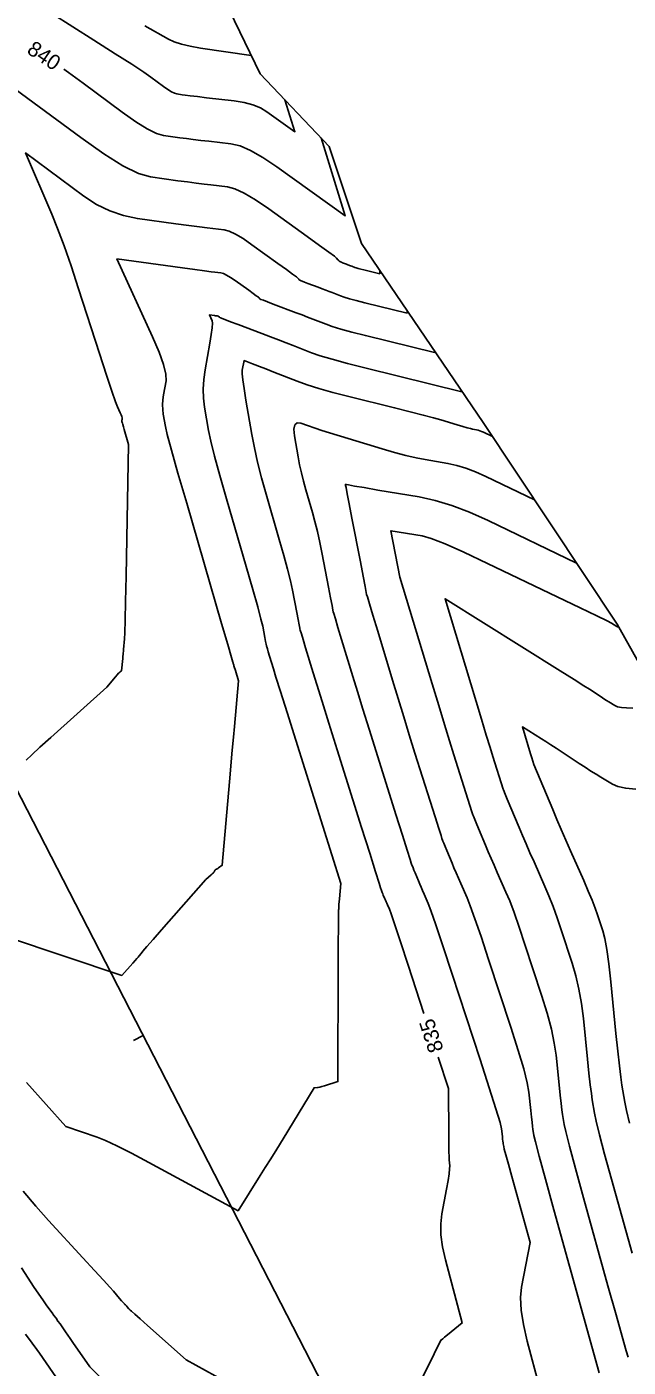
# Model space of a CAD drawing. Extents: x 1715724 to 1716561, y 394063 to 395906.
# Drawn here: x 1716015.3 to 1716070.7, y 395089 to 395212.3 of the extents above; entities that cross this region are included whole.
import ezdxf

# ---------------------------------------------------------------- set-up
doc = ezdxf.new("R2010")
doc.units = 0
for name, color, linetype in [('DT_X_Contour_Major', 7, 'Continuous'), ('DT_X_Contour_Minor', 7, 'Continuous'), ('DT_X_TIN_Hull', 7, 'Continuous'), ('GE_P_CL_10', 7, 'Continuous')]:
    doc.layers.add(name, color=color, linetype=linetype)

msp = doc.modelspace()

# ---------------------------------------------------------------- linework, layer by layer
at = {"layer": 'DT_X_Contour_Major'}
for points in [[(1716018.73, 395208.41), (1716019.18, 395208.1), (1716020.51, 395207.13), (1716024.11, 395204.46), (1716025.36, 395203.58), (1716026.42, 395202.92), (1716027.28, 395202.5), (1716027.93, 395202.31), (1716029.43, 395202.1), (1716030.02, 395202.03), (1716030.65, 395201.94), (1716031.34, 395201.86), (1716032.08, 395201.78), (1716034.12, 395201.54), (1716034.96, 395201.35), (1716035.94, 395200.93), (1716037.07, 395200.29), (1716038.35, 395199.43), (1716044.64, 395194.91), (1716042.42, 395202.1)], [(1716051.9, 395121.49), (1716050.44, 395125.94), (1716049.73, 395128.09), (1716049.21, 395129.66), (1716048.87, 395130.67), (1716048.71, 395131.1), (1716048.54, 395131.5), (1716048.47, 395131.65), (1716048.41, 395131.79), (1716048.35, 395131.92), (1716048.3, 395132.05), (1716048.15, 395132.4), (1716048.1, 395132.52), (1716048.06, 395132.63), (1716048.02, 395132.74), (1716047.99, 395132.83), (1716047.9, 395133.08), (1716047.77, 395133.49), (1716047.44, 395134.55), (1716046.9, 395136.26), (1716046.15, 395138.62), (1716043.9, 395145.78), (1716043.13, 395148.23), (1716042.51, 395150.23), (1716042.03, 395151.78), (1716041.7, 395152.86), (1716041, 395155.16), (1716040.77, 395155.91), (1716040.61, 395156.45), (1716040.51, 395156.78), (1716040.48, 395156.89), (1716040.48, 395156.89), (1716040.46, 395156.98), (1716040.4, 395157.27), (1716040.31, 395157.75), (1716040.18, 395158.42), (1716039.79, 395160.46), (1716039.6, 395161.33), (1716039.34, 395162.4), (1716039, 395163.66), (1716038.58, 395165.13), (1716037.36, 395169.3), (1716036.94, 395170.81), (1716036.58, 395172.24), (1716036.28, 395173.56), (1716036.04, 395174.79), (1716035.51, 395177.95), (1716035.33, 395179.01), (1716035.22, 395179.82), (1716035.17, 395180.38), (1716035.17, 395180.7), (1716035.33, 395181.59), (1716036.11, 395181.3), (1716036.36, 395181.2), (1716036.77, 395181.04), (1716037.33, 395180.82), (1716038.06, 395180.54), (1716040.22, 395179.69), (1716041.13, 395179.36), (1716042.22, 395179.02), (1716043.51, 395178.66), (1716044.99, 395178.28), (1716049.19, 395177.25), (1716050.64, 395176.88), (1716051.83, 395176.58), (1716052.77, 395176.33), (1716053.46, 395176.13), (1716054.96, 395175.67), (1716055.47, 395175.52), (1716055.87, 395175.4), (1716056.17, 395175.33), (1716056.37, 395175.28), (1716056.75, 395175.22), (1716056.9, 395175.19), (1716057.05, 395175.14), (1716057.21, 395175.08), (1716057.38, 395175), (1716058.2, 395174.61)], [(1716071.39, 395142.15), (1716070.47, 395142.24), (1716069.76, 395142.39), (1716069.25, 395142.6), (1716068.17, 395143.26), (1716067.74, 395143.53), (1716067.27, 395143.82), (1716066.75, 395144.16), (1716066.19, 395144.52), (1716064.07, 395145.91), (1716063.57, 395146.24), (1716063.12, 395146.53), (1716062.71, 395146.78), (1716060.96, 395147.88), (1716061.71, 395145.4), (1716061.83, 395145.02), (1716062.02, 395144.41), (1716063.75, 395140.28), (1716064.13, 395139.37), (1716064.53, 395138.44), (1716064.96, 395137.46), (1716065.4, 395136.46), (1716066.61, 395133.73), (1716067.03, 395132.76), (1716067.38, 395131.92), (1716067.67, 395131.19), (1716067.88, 395130.58), (1716068.36, 395129.11), (1716068.54, 395128.41), (1716068.72, 395127.39), (1716068.91, 395126.07), (1716069.09, 395124.43), (1716069.57, 395119.66), (1716069.74, 395118.03), (1716069.89, 395116.69), (1716070.02, 395115.65), (1716070.13, 395114.91), (1716070.38, 395113.33), (1716070.54, 395112.56), (1716070.81, 395111.4)], [(1716051.48, 395087.48), (1716052.27, 395089.05), (1716052.84, 395090.19), (1716053.19, 395090.9), (1716053.32, 395091.17), (1716053.45, 395091.44), (1716053.46, 395091.45), (1716053.5, 395091.48), (1716053.62, 395091.57), (1716053.8, 395091.72), (1716054.06, 395091.93), (1716055.43, 395093.03), (1716053.88, 395098.83), (1716053.61, 395100.03), (1716053.46, 395101.13), (1716053.44, 395102.13), (1716053.54, 395103.05), (1716053.98, 395105.35), (1716054.12, 395106.13), (1716054.21, 395106.75), (1716054.26, 395107.2), (1716054.27, 395107.48), (1716054.23, 395108.02), (1716054.21, 395108.32), (1716054.2, 395108.79), (1716054.19, 395109.45), (1716054.18, 395110.28), (1716054.15, 395114.6), (1716053.21, 395117.49)], [(1716015, 395105.15), (1716016.15, 395103.76), (1716017.32, 395102.44), (1716020.49, 395099.01), (1716021.56, 395097.86), (1716022.38, 395096.96), (1716022.96, 395096.33), (1716023.3, 395095.95), (1716023.87, 395095.28), (1716024.06, 395095.07), (1716024.2, 395094.91), (1716024.29, 395094.81), (1716024.32, 395094.77), (1716024.34, 395094.75), (1716024.35, 395094.74), (1716024.36, 395094.73), (1716024.37, 395094.72), (1716024.38, 395094.71), (1716024.42, 395094.67), (1716024.44, 395094.66), (1716024.47, 395094.63), (1716024.5, 395094.59), (1716024.53, 395094.55), (1716024.71, 395094.32), (1716024.85, 395094.2), (1716024.97, 395094.1), (1716025.28, 395093.83), (1716025.77, 395093.4), (1716026.44, 395092.8), (1716030.01, 395089.64), (1716034.44, 395087.17)]]:
    msp.add_lwpolyline(points, dxfattribs=at)
at = {"layer": 'DT_X_Contour_Minor'}
for points in [[(1716015.7, 395214.75), (1716021.51, 395211.08), (1716023.47, 395209.84), (1716025, 395208.86), (1716026.09, 395208.14), (1716026.74, 395207.68), (1716027.91, 395206.82), (1716028.31, 395206.54), (1716028.65, 395206.32), (1716028.93, 395206.19), (1716029.14, 395206.13), (1716029.62, 395206.06), (1716029.9, 395206.02), (1716030.37, 395205.97), (1716031.04, 395205.89), (1716031.89, 395205.79), (1716034.43, 395205.5), (1716035.33, 395205.36), (1716036.13, 395205.14), (1716036.84, 395204.85), (1716037.44, 395204.49), (1716040.01, 395202.65), (1716039.1, 395205.58)], [(1716026.2, 395212.41), (1716028.37, 395211.18), (1716028.91, 395210.93), (1716029.57, 395210.71), (1716030.38, 395210.52), (1716031.31, 395210.35), (1716035.99, 395209.67)], [(1716014.27, 395206.58), (1716020.31, 395202.11), (1716022.41, 395200.62), (1716024.18, 395199.52), (1716025.62, 395198.81), (1716026.73, 395198.49), (1716029.24, 395198.15), (1716030.13, 395198.03), (1716030.93, 395197.92), (1716031.65, 395197.83), (1716032.27, 395197.76), (1716033.81, 395197.58), (1716034.48, 395197.41), (1716035.34, 395197.01), (1716036.38, 395196.39), (1716037.61, 395195.55), (1716041.13, 395193.02), (1716042.29, 395192.19), (1716043.13, 395191.57), (1716043.65, 395191.19), (1716043.86, 395191.02), (1716043.98, 395190.88), (1716044.02, 395190.83), (1716044.05, 395190.79), (1716044.08, 395190.76), (1716044.09, 395190.75), (1716044.12, 395190.72), (1716044.15, 395190.71), (1716044.2, 395190.68), (1716044.29, 395190.65), (1716044.41, 395190.6), (1716044.77, 395190.47), (1716044.9, 395190.42), (1716045.14, 395190.32), (1716045.25, 395190.28), (1716045.53, 395190.17), (1716045.66, 395190.13), (1716045.85, 395190.07), (1716046.08, 395190.01), (1716046.37, 395189.94), (1716047.83, 395189.58), (1716047.84, 395189.6), (1716047.84, 395189.62), (1716047.84, 395189.63), (1716047.84, 395189.66), (1716047.84, 395189.7), (1716047.84, 395189.89)], [(1716015.27, 395144.83), (1716015.79, 395145.31), (1716016.54, 395146), (1716017.53, 395146.89), (1716022.69, 395151.53), (1716023.5, 395152.49), (1716023.66, 395152.67), (1716023.78, 395152.81), (1716023.87, 395152.9), (1716023.92, 395152.94), (1716024.06, 395153.04), (1716024.16, 395154.18), (1716024.18, 395154.4), (1716024.19, 395154.55), (1716024.2, 395154.67), (1716024.2, 395154.67), (1716024.21, 395154.71), (1716024.22, 395154.81), (1716024.23, 395154.99), (1716024.32, 395155.98), (1716024.35, 395156.55), (1716024.38, 395157.7), (1716024.42, 395159.43), (1716024.47, 395161.74), (1716024.69, 395173.88), (1716024.29, 395175.25), (1716024.22, 395175.51), (1716024.16, 395175.71), (1716024.13, 395175.84), (1716024.11, 395175.91), (1716024.09, 395176), (1716024.09, 395176.04), (1716024.09, 395176.08), (1716024.09, 395176.12), (1716024.1, 395176.16), (1716024.12, 395176.27), (1716024.11, 395176.33), (1716024.08, 395176.44), (1716024.02, 395176.59), (1716023.93, 395176.78), (1716023.67, 395177.35), (1716023.5, 395177.81), (1716023.16, 395178.79), (1716022.68, 395180.26), (1716022.03, 395182.24), (1716020.1, 395188.2), (1716019.41, 395190.31), (1716018.76, 395192.16), (1716018.17, 395193.75), (1716017.63, 395195.08), (1716015.22, 395200.71), (1716020.58, 395196.74), (1716021.75, 395195.97), (1716022.97, 395195.37), (1716024.22, 395194.94), (1716025.52, 395194.67), (1716029.04, 395194.19), (1716030.24, 395194.03), (1716031.22, 395193.9), (1716031.95, 395193.8), (1716032.46, 395193.74), (1716033.5, 395193.62), (1716033.95, 395193.5), (1716034.53, 395193.24), (1716035.24, 395192.82), (1716036.06, 395192.25), (1716038.44, 395190.54), (1716039.23, 395189.98), (1716039.8, 395189.56), (1716040.15, 395189.3), (1716040.29, 395189.19), (1716040.37, 395189.09), (1716040.42, 395189.03), (1716040.44, 395189.02), (1716040.45, 395189.01), (1716040.46, 395188.99), (1716040.52, 395188.97), (1716040.89, 395188.82), (1716041.2, 395188.7), (1716042.17, 395188.34), (1716042.52, 395188.21), (1716042.85, 395188.08), (1716043.16, 395187.96), (1716043.46, 395187.85), (1716044.2, 395187.55), (1716044.55, 395187.43), (1716045.04, 395187.28), (1716045.67, 395187.11), (1716046.44, 395186.92), (1716050.34, 395185.96), (1716050.35, 395185.98), (1716050.35, 395185.99), (1716050.35, 395186), (1716050.35, 395186.02), (1716050.35, 395186.05), (1716050.36, 395186.19)], [(1716013.56, 395128.54), (1716024.09, 395125.01), (1716025.1, 395126.14), (1716025.3, 395126.37), (1716025.46, 395126.55), (1716025.59, 395126.7), (1716025.67, 395126.8), (1716025.85, 395127.03), (1716026.02, 395127.23), (1716026.39, 395127.66), (1716026.97, 395128.31), (1716027.74, 395129.19), (1716031.82, 395133.82), (1716032.31, 395134.26), (1716032.4, 395134.35), (1716032.48, 395134.42), (1716032.53, 395134.49), (1716032.57, 395134.54), (1716032.63, 395134.65), (1716032.66, 395134.69), (1716032.68, 395134.72), (1716032.7, 395134.75), (1716032.73, 395134.76), (1716032.78, 395134.79), (1716032.81, 395134.8), (1716032.85, 395134.83), (1716032.91, 395134.86), (1716032.97, 395134.9), (1716033.32, 395135.14), (1716033.99, 395142.82), (1716034.25, 395145.74), (1716034.36, 395146.92), (1716034.45, 395147.92), (1716034.83, 395152.12), (1716034.53, 395153.08), (1716034.43, 395153.4), (1716034.4, 395153.5), (1716034.38, 395153.56), (1716034.36, 395153.64), (1716034.35, 395153.67), (1716034.34, 395153.7), (1716034.34, 395153.71), (1716034.33, 395153.71), (1716034.33, 395153.72), (1716034.33, 395153.73), (1716034.32, 395153.77), (1716034.31, 395153.85), (1716034.19, 395154.27), (1716033.84, 395155.45), (1716033.27, 395157.41), (1716030.05, 395168.46), (1716029.25, 395171.24), (1716028.65, 395173.35), (1716028.26, 395174.78), (1716028.09, 395175.54), (1716027.9, 395176.65), (1716027.85, 395177.08), (1716027.83, 395177.52), (1716027.86, 395177.98), (1716027.93, 395178.45), (1716028.15, 395179.73), (1716028.14, 395180.34), (1716027.93, 395181.22), (1716027.52, 395182.36), (1716026.91, 395183.77), (1716023.62, 395190.95), (1716029.66, 395190.12), (1716030.81, 395189.97), (1716031.7, 395189.85), (1716032.31, 395189.77), (1716032.65, 395189.72), (1716033.19, 395189.66), (1716033.43, 395189.6), (1716033.73, 395189.46), (1716034.09, 395189.24), (1716034.52, 395188.95), (1716035.76, 395188.06), (1716036.17, 395187.77), (1716036.46, 395187.55), (1716036.65, 395187.42), (1716036.72, 395187.36), (1716036.76, 395187.31), (1716036.78, 395187.29), (1716036.79, 395187.28), (1716036.8, 395187.27), (1716036.8, 395187.26), (1716036.81, 395187.25), (1716036.89, 395187.22), (1716037.11, 395187.14), (1716037.48, 395187), (1716038, 395186.8), (1716040.14, 395186), (1716040.68, 395185.79), (1716041.18, 395185.59), (1716041.66, 395185.41), (1716042.88, 395184.93), (1716043.45, 395184.73), (1716044.24, 395184.49), (1716045.26, 395184.22), (1716046.51, 395183.9), (1716052.86, 395182.34), (1716052.87, 395182.35), (1716052.87, 395182.36), (1716052.87, 395182.37), (1716052.87, 395182.38), (1716052.87, 395182.4), (1716052.87, 395182.49)], [(1716015.31, 395115.15), (1716018.92, 395111.09), (1716021.82, 395110.12), (1716022.58, 395109.82), (1716023.63, 395109.33), (1716024.96, 395108.66), (1716026.58, 395107.8), (1716034.78, 395103.35), (1716036.83, 395106.58), (1716037.29, 395107.32), (1716037.8, 395108.13), (1716038.34, 395109.01), (1716038.93, 395109.98), (1716041.78, 395114.67), (1716042.08, 395114.69), (1716042.17, 395114.7), (1716042.31, 395114.73), (1716042.5, 395114.79), (1716042.74, 395114.86), (1716043.97, 395115.23), (1716044.01, 395125.97), (1716044.01, 395127.99), (1716044.02, 395129.46), (1716044.02, 395130.37), (1716044.03, 395130.74), (1716044.04, 395130.96), (1716044.04, 395131.04), (1716044.05, 395131.11), (1716044.05, 395131.17), (1716044.05, 395131.22), (1716044.05, 395131.35), (1716044.05, 395131.43), (1716044.06, 395131.57), (1716044.08, 395131.78), (1716044.11, 395132.06), (1716044.24, 395133.48), (1716040.09, 395146.66), (1716039.29, 395149.19), (1716038.69, 395151.13), (1716038.27, 395152.47), (1716038.04, 395153.21), (1716037.68, 395154.4), (1716037.56, 395154.79), (1716037.48, 395155.07), (1716037.42, 395155.24), (1716037.41, 395155.3), (1716037.4, 395155.35), (1716037.37, 395155.5), (1716037.32, 395155.75), (1716037.25, 395156.1), (1716037.05, 395157.16), (1716036.89, 395157.8), (1716036.59, 395158.92), (1716036.13, 395160.54), (1716035.53, 395162.64), (1716033.71, 395168.88), (1716033.09, 395171.03), (1716032.61, 395172.79), (1716032.27, 395174.17), (1716032.07, 395175.17), (1716031.7, 395177.3), (1716031.6, 395178.12), (1716031.58, 395178.96), (1716031.63, 395179.84), (1716031.75, 395180.74), (1716032.19, 395183.19), (1716032.32, 395184), (1716032.4, 395184.62), (1716032.43, 395185.04), (1716032.4, 395185.25), (1716032.15, 395185.8), (1716032.61, 395185.74), (1716032.7, 395185.72), (1716032.77, 395185.72), (1716032.84, 395185.71), (1716032.88, 395185.7), (1716032.9, 395185.7), (1716032.92, 395185.69), (1716032.95, 395185.67), (1716033.08, 395185.58), (1716033.11, 395185.56), (1716033.13, 395185.54), (1716033.14, 395185.53), (1716033.15, 395185.53), (1716033.15, 395185.52), (1716033.15, 395185.52), (1716033.15, 395185.52), (1716033.15, 395185.52), (1716033.16, 395185.52), (1716033.56, 395185.37), (1716034.07, 395185.17), (1716034.79, 395184.9), (1716036.96, 395184.08), (1716037.76, 395183.78), (1716038.5, 395183.5), (1716039.2, 395183.23), (1716039.86, 395182.97), (1716041.55, 395182.31), (1716042.34, 395182.04), (1716043.44, 395181.71), (1716044.86, 395181.32), (1716046.58, 395180.89), (1716055.38, 395178.72), (1716055.38, 395178.73), (1716055.38, 395178.78)], [(1716062.55, 395087.1), (1716061.41, 395091.36), (1716061.06, 395092.87), (1716060.85, 395094.2), (1716060.79, 395095.35), (1716060.89, 395096.31), (1716061.67, 395100.42), (1716059.98, 395106.49), (1716059.67, 395107.64), (1716059.44, 395108.49), (1716059.29, 395109.03), (1716059.24, 395109.27), (1716059.2, 395109.5), (1716059.18, 395109.6), (1716059.16, 395109.76), (1716059.14, 395109.95), (1716059.12, 395110.19), (1716059.05, 395110.88), (1716058.9, 395111.48), (1716058.53, 395112.74), (1716057.91, 395114.67), (1716057.07, 395117.28), (1716054.5, 395125.11), (1716053.64, 395127.72), (1716052.99, 395129.67), (1716052.54, 395130.98), (1716052.29, 395131.63), (1716051.91, 395132.49), (1716051.77, 395132.81), (1716051.64, 395133.12), (1716051.51, 395133.41), (1716051.39, 395133.7), (1716051.08, 395134.44), (1716050.97, 395134.7), (1716050.89, 395134.9), (1716050.83, 395135.05), (1716050.79, 395135.15), (1716050.73, 395135.35), (1716050.62, 395135.68), (1716050.35, 395136.54), (1716049.91, 395137.93), (1716049.31, 395139.83), (1716047.49, 395145.62), (1716046.84, 395147.68), (1716046.27, 395149.52), (1716045.77, 395151.13), (1716045.35, 395152.52), (1716044.32, 395155.92), (1716043.98, 395157.04), (1716043.74, 395157.83), (1716043.6, 395158.31), (1716043.55, 395158.47), (1716043.55, 395158.47), (1716043.52, 395158.62), (1716043.44, 395159.04), (1716043.3, 395159.75), (1716043.11, 395160.75), (1716042.53, 395163.77), (1716042.31, 395164.86), (1716042.08, 395165.87), (1716041.86, 395166.78), (1716041.63, 395167.62), (1716041.02, 395169.71), (1716040.8, 395170.49), (1716040.61, 395171.26), (1716040.45, 395172), (1716040.31, 395172.73), (1716039.98, 395174.66), (1716039.93, 395175.28), (1716040, 395175.68), (1716040.22, 395175.86), (1716040.56, 395175.82), (1716042.49, 395175.17), (1716048.05, 395173.48), (1716049.19, 395173.14), (1716050.23, 395172.87), (1716051.17, 395172.65), (1716052.01, 395172.48), (1716054.1, 395172.13), (1716054.91, 395171.95), (1716055.76, 395171.7), (1716056.65, 395171.36), (1716057.59, 395170.94), (1716062.07, 395168.79)], [(1716068.02, 395088.44), (1716063.87, 395103.44), (1716063.09, 395106.27), (1716062.52, 395108.36), (1716062.16, 395109.7), (1716062.02, 395110.28), (1716061.93, 395110.85), (1716061.89, 395111.11), (1716061.85, 395111.49), (1716061.79, 395111.97), (1716061.73, 395112.56), (1716061.56, 395114.27), (1716061.4, 395115.13), (1716061.08, 395116.4), (1716060.57, 395118.11), (1716059.89, 395120.24), (1716057.85, 395126.47), (1716057.15, 395128.58), (1716056.59, 395130.23), (1716056.16, 395131.42), (1716055.87, 395132.15), (1716055.28, 395133.48), (1716055.07, 395133.97), (1716054.86, 395134.45), (1716054.66, 395134.9), (1716054.48, 395135.34), (1716054, 395136.49), (1716053.84, 395136.87), (1716053.72, 395137.17), (1716053.64, 395137.36), (1716053.6, 395137.47), (1716053.55, 395137.61), (1716053.47, 395137.87), (1716053.26, 395138.53), (1716052.93, 395139.59), (1716052.47, 395141.05), (1716051.07, 395145.47), (1716050.55, 395147.14), (1716050.04, 395148.81), (1716049.52, 395150.49), (1716049.01, 395152.17), (1716047.64, 395156.68), (1716047.2, 395158.16), (1716046.88, 395159.22), (1716046.69, 395159.85), (1716046.62, 395160.06), (1716046.62, 395160.06), (1716046.58, 395160.25), (1716046.48, 395160.81), (1716046.29, 395161.75), (1716046.04, 395163.07), (1716045.27, 395167.08), (1716045.01, 395168.4), (1716044.83, 395169.34), (1716044.72, 395169.91), (1716044.68, 395170.11), (1716044.67, 395170.13), (1716044.67, 395170.14), (1716044.67, 395170.15), (1716044.66, 395170.16), (1716044.66, 395170.17), (1716044.66, 395170.2), (1716044.66, 395170.2), (1716044.66, 395170.21), (1716044.66, 395170.21), (1716044.67, 395170.21), (1716044.69, 395170.2), (1716044.76, 395170.18), (1716044.95, 395170.15), (1716045.5, 395170.05), (1716046.4, 395169.9), (1716047.65, 395169.68), (1716051.45, 395169.04), (1716052.92, 395168.72), (1716054.47, 395168.25), (1716056.09, 395167.64), (1716057.8, 395166.87), (1716065.95, 395162.96)], [(1716069.84, 395157.09), (1716069.73, 395157.09), (1716069.7, 395157.09), (1716069.68, 395157.1), (1716069.67, 395157.11), (1716069.41, 395157.27), (1716069.15, 395157.43), (1716068.77, 395157.63), (1716067.81, 395158.1), (1716066.27, 395158.84), (1716064.15, 395159.86), (1716057.75, 395162.93), (1716055.57, 395163.96), (1716053.84, 395164.72), (1716052.56, 395165.21), (1716051.72, 395165.45), (1716048.86, 395165.94), (1716049.69, 395161.65), (1716052.66, 395151.83), (1716053.27, 395149.84), (1716053.8, 395148.1), (1716054.26, 395146.59), (1716054.66, 395145.32), (1716056.32, 395140.06), (1716056.37, 395139.88), (1716056.41, 395139.78), (1716056.45, 395139.67), (1716056.71, 395139.05), (1716056.92, 395138.54), (1716057.57, 395136.99), (1716057.82, 395136.39), (1716058.08, 395135.78), (1716058.36, 395135.14), (1716058.65, 395134.47), (1716059.45, 395132.68), (1716059.79, 395131.87), (1716060.19, 395130.79), (1716060.66, 395129.45), (1716061.19, 395127.84), (1716062.72, 395123.19), (1716063.23, 395121.54), (1716063.63, 395120.07), (1716063.9, 395118.77), (1716064.07, 395117.66), (1716064.34, 395114.93), (1716064.44, 395113.99), (1716064.53, 395113.22), (1716064.6, 395112.63), (1716064.66, 395112.2), (1716064.81, 395111.3), (1716064.96, 395110.63), (1716065.31, 395109.28), (1716065.86, 395107.25), (1716066.6, 395104.55), (1716068.84, 395096.45), (1716069.59, 395093.77), (1716070.15, 395091.77), (1716070.52, 395090.47), (1716070.7, 395089.86)], [(1716071.12, 395149.61), (1716070.56, 395149.62), (1716070.09, 395149.66), (1716069.73, 395149.74), (1716069.47, 395149.85), (1716068.92, 395150.18), (1716068.71, 395150.32), (1716068.46, 395150.47), (1716068.2, 395150.64), (1716067.13, 395151.34), (1716066.63, 395151.66), (1716065.73, 395152.23), (1716064.43, 395153.05), (1716053.84, 395159.67), (1716057.19, 395148.6), (1716057.64, 395147.12), (1716057.99, 395145.97), (1716058.25, 395145.17), (1716059.19, 395142.15), (1716059.21, 395142.1), (1716059.38, 395141.7), (1716059.57, 395141.23), (1716060.66, 395138.63), (1716060.98, 395137.88), (1716061.31, 395137.11), (1716061.66, 395136.3), (1716062.03, 395135.47), (1716063.03, 395133.2), (1716063.41, 395132.32), (1716063.79, 395131.36), (1716064.16, 395130.32), (1716064.54, 395129.21), (1716065.54, 395126.15), (1716065.89, 395124.97), (1716066.17, 395123.73), (1716066.4, 395122.42), (1716066.58, 395121.05), (1716066.96, 395117.3), (1716067.09, 395116.01), (1716067.21, 395114.95), (1716067.31, 395114.14), (1716067.39, 395113.55), (1716067.6, 395112.32), (1716067.75, 395111.59), (1716068.06, 395110.34), (1716068.53, 395108.56), (1716069.17, 395106.26), (1716071.06, 395099.43)], [(1716014.83, 395098.08), (1716016.02, 395096.3), (1716016.8, 395095.14), (1716017.18, 395094.59), (1716017.65, 395093.96), (1716017.83, 395093.71), (1716018.02, 395093.46), (1716018.2, 395093.2), (1716018.39, 395092.93), (1716018.9, 395092.19), (1716019.11, 395091.9), (1716019.33, 395091.58), (1716019.57, 395091.23), (1716021.13, 395088.98), (1716024.61, 395085.54)], [(1716015.2, 395091.99), (1716015.82, 395091.16), (1716016.25, 395090.57), (1716016.49, 395090.24), (1716021.14, 395083.53)]]:
    msp.add_lwpolyline(points, dxfattribs=at)
at = {"layer": 'DT_X_TIN_Hull'}
msp.add_lwpolyline([(1716081.11, 395137.01), (1716069.7, 395157.33), (1716057.34, 395175.9), (1716046.15, 395192.38), (1716043.18, 395201.3), (1716036.81, 395207.99), (1716026.44, 395229.43)], dxfattribs=at)
at = {"layer": 'GE_P_CL_10'}
for p, q in [((1716249.46, 394685.42), (1715852.54, 395456.56)), ((1716026.04, 395119.49), (1716025.15, 395119.03))]:
    msp.add_line(p, q, dxfattribs=at)

# ---------------------------------------------------------------- texts
at = {"layer": 'DT_X_Contour_Major'}
for s, rotation, p in [('840', 326.1777, (1716015.24, 395209.95)), ('835', 108.1386, (1716053.72, 395118.18))]:
    msp.add_text(s, height=1.4, rotation=rotation, dxfattribs=at).set_placement(p)

doc.saveas('drawing.dxf')
